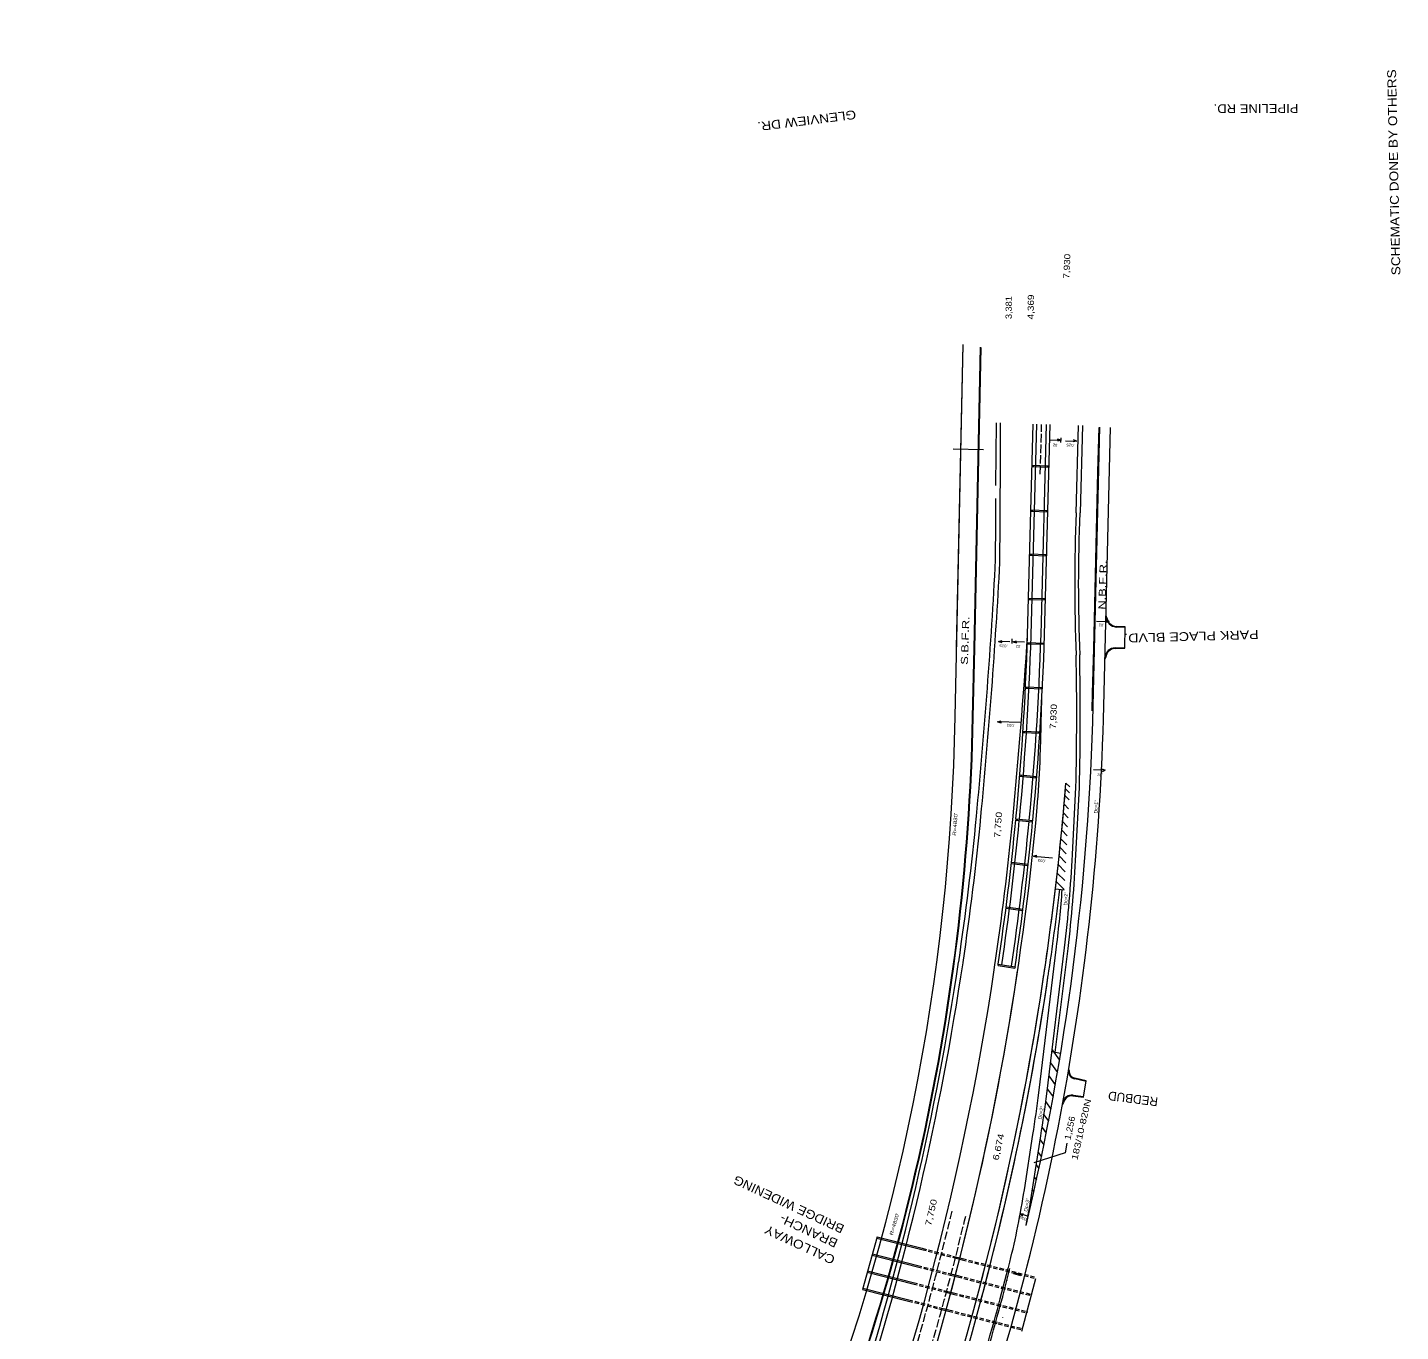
# Model space of a CAD drawing. Extents: x 2354993 to 2372084, y 6966390 to 6990057.
# Drawn here: x 2364099 to 2367196, y 6983254 to 6986197 of the extents above; entities that cross this region are included whole.
import ezdxf

# ---------------------------------------------------------------- set-up
doc = ezdxf.new("R2010")
doc.units = 0
doc.header["$LTSCALE"] = 3.2
doc.linetypes.add('LONG_DASHED', pattern=[7.5, 6, -1.5])
doc.linetypes.add('MEDIUM_DASHED', pattern=[4.5, 3, -1.5])
for name, color, linetype, lineweight in [('11', 7, 'Continuous', 13), ('12', 7, 'Continuous', 13), ('13', 7, 'Continuous', 13), ('19', 7, 'Continuous', 13), ('25', 7, 'Continuous', 13), ('4', 7, 'Continuous', 13), ('40', 7, 'Continuous', 13), ('5', 7, 'Continuous', 13), ('6', 7, 'Continuous', 13), ('63', 7, 'Continuous', 13), ('7', 7, 'Continuous', 13), ('8', 7, 'Continuous', 13), ('9', 7, 'Continuous', 13)]:
    doc.layers.add(name, color=color, linetype=linetype, lineweight=lineweight)

msp = doc.modelspace()

# ---------------------------------------------------------------- linework, layer by layer
at = {"layer": '11'}
for p, q in [((2366538.791, 6984856.255), (2366530.724, 6984854.262)), ((2366529.954, 6984521.156), (2366503.645, 6984521.922)), ((2366523.004, 6984523.998), (2366529.954, 6984521.156)), ((2366523.876, 6984518.238), (2366529.954, 6984521.156))]:
    msp.add_line(p, q, dxfattribs=at)
msp.add_lwpolyline([(2366510.454, 6984857.25), (2366538.791, 6984856.255), (2366530.884, 6984858.81)], dxfattribs=at)
at = {"layer": '12'}
for p, q in [((2366364.888, 6985208.936), (2366364.805, 6985205.936)), ((2366364.805, 6985205.936), (2366403.044, 6985204.915)), ((2366364.888, 6985208.936), (2366403.118, 6985207.914)), ((2366367.987, 6985208.85), (2366367.904, 6985205.85)), ((2366399.945, 6985204.992), (2366400.019, 6985207.991)), ((2366403.044, 6985204.915), (2366403.118, 6985207.914)), ((2366362.436, 6985108.243), (2366362.353, 6985105.243)), ((2366362.353, 6985105.243), (2366400.592, 6985104.222)), ((2366362.436, 6985108.243), (2366400.666, 6985107.221)), ((2366365.535, 6985108.157), (2366365.452, 6985105.157)), ((2366397.493, 6985104.299), (2366397.567, 6985107.298)), ((2366400.592, 6985104.222), (2366400.666, 6985107.221)), ((2366359.998, 6985008.861), (2366359.915, 6985005.861)), ((2366359.915, 6985005.861), (2366398.154, 6985004.84)), ((2366359.998, 6985008.861), (2366398.228, 6985007.839)), ((2366363.097, 6985008.775), (2366363.014, 6985005.775)), ((2366395.055, 6985004.917), (2366395.129, 6985007.916)), ((2366398.154, 6985004.84), (2366398.228, 6985007.839)), ((2366357.049, 6984909.117), (2366356.966, 6984906.117)), ((2366356.966, 6984906.117), (2366395.205, 6984905.096)), ((2366357.049, 6984909.117), (2366395.279, 6984908.095)), ((2366360.148, 6984909.031), (2366360.065, 6984906.031)), ((2366392.106, 6984905.173), (2366392.18, 6984908.172)), ((2366395.205, 6984905.096), (2366395.279, 6984908.095)), ((2366354.588, 6984808.904), (2366354.505, 6984805.904)), ((2366354.505, 6984805.904), (2366392.744, 6984804.883)), ((2366354.588, 6984808.904), (2366392.818, 6984807.882)), ((2366357.687, 6984808.818), (2366357.604, 6984805.818)), ((2366389.645, 6984804.96), (2366389.719, 6984807.959)), ((2366392.744, 6984804.883), (2366392.818, 6984807.882)), ((2366350.209, 6984708.655), (2366350.126, 6984705.655)), ((2366350.126, 6984705.655), (2366388.365, 6984704.634)), ((2366350.209, 6984708.655), (2366388.439, 6984707.633)), ((2366353.308, 6984708.569), (2366353.225, 6984705.569)), ((2366385.266, 6984704.711), (2366385.34, 6984707.71)), ((2366388.365, 6984704.634), (2366388.439, 6984707.633)), ((2366344.53, 6984608.98), (2366344.406, 6984605.981)), ((2366344.406, 6984605.981), (2366382.629, 6984604.439)), ((2366344.53, 6984608.98), (2366382.743, 6984607.436)), ((2366347.628, 6984608.852), (2366347.504, 6984605.853)), ((2366379.531, 6984604.558), (2366379.646, 6984607.555)), ((2366382.629, 6984604.439), (2366382.743, 6984607.436)), ((2366338.161, 6984510.231), (2366337.864, 6984507.244)), ((2366338.161, 6984510.231), (2366376.221, 6984506.482)), ((2366341.246, 6984509.924), (2366340.949, 6984506.937)), ((2366337.864, 6984507.244), (2366375.933, 6984503.496)), ((2366372.847, 6984503.794), (2366373.135, 6984506.78)), ((2366375.933, 6984503.496), (2366376.221, 6984506.482)), ((2366328.743, 6984410.781), (2366328.446, 6984407.794)), ((2366328.446, 6984407.794), (2366366.515, 6984404.046)), ((2366328.743, 6984410.781), (2366366.803, 6984407.032)), ((2366331.828, 6984410.474), (2366331.531, 6984407.487)), ((2366363.429, 6984404.344), (2366363.717, 6984407.33)), ((2366366.515, 6984404.046), (2366366.803, 6984407.032)), ((2366318.344, 6984310.299), (2366356.373, 6984306.191)), ((2366318.666, 6984313.282), (2366356.695, 6984309.174)), ((2366306.287, 6984209.38), (2366344.232, 6984204.566)), ((2366306.665, 6984212.356), (2366344.611, 6984207.542)), ((2366288.504, 6984080.134), (2366288.942, 6984083.102)), ((2366288.504, 6984080.134), (2366326.343, 6984074.539)), ((2366288.942, 6984083.102), (2366326.781, 6984077.507)), ((2366326.781, 6984077.507), (2366326.343, 6984074.539)), ((2366015.164, 6983465.056), (2366116.698, 6983439.228)), ((2366015.904, 6983467.964), (2366117.457, 6983442.131)), ((2366004.286, 6983426.55), (2366106.578, 6983400.527)), ((2366005.097, 6983429.441), (2366107.337, 6983403.431)), ((2366186.244, 6983424.631), (2366208.214, 6983419.041)), ((2366185.481, 6983421.728), (2366207.447, 6983416.14)), ((2366306.379, 6983394.068), (2366312.798, 6983392.434)), ((2365993.478, 6983388.025), (2366096.459, 6983361.827)), ((2365994.288, 6983390.915), (2366097.218, 6983364.731)), ((2366175.316, 6983383.04), (2366197.226, 6983377.466)), ((2366176.078, 6983385.942), (2366197.993, 6983380.366)), ((2366305.608, 6983391.166), (2366312.143, 6983389.503)), ((2366323.39, 6983384.946), (2366339.177, 6983380.553)), ((2366324.132, 6983387.855), (2366339.955, 6983383.452)), ((2366342.248, 6983255.14), (2366373.814, 6983374.03)), ((2365982.67, 6983349.503), (2366086.339, 6983323.127)), ((2365983.481, 6983352.393), (2366087.098, 6983326.03)), ((2366165.15, 6983344.352), (2366187.006, 6983338.792)), ((2366165.913, 6983347.255), (2366187.773, 6983341.694)), ((2366295.329, 6983352.508), (2366303.407, 6983350.453)), ((2366296.1, 6983355.408), (2366304.062, 6983353.382)), ((2366154.985, 6983305.663), (2366176.785, 6983300.117)), ((2366155.748, 6983308.565), (2366177.552, 6983303.018)), ((2366285.049, 6983313.848), (2366294.672, 6983311.4)), ((2366285.821, 6983316.75), (2366295.327, 6983314.331)), ((2366274.77, 6983275.189), (2366285.936, 6983272.348)), ((2366275.541, 6983278.088), (2366286.591, 6983275.277))]:
    msp.add_line(p, q, dxfattribs=at)
at = {"layer": '12', "linetype": 'MEDIUM_DASHED'}
for p, q in [((2366116.698, 6983439.227), (2366185.481, 6983421.728)), ((2366117.457, 6983442.13), (2366186.244, 6983424.631)), ((2366106.578, 6983400.528), (2366175.316, 6983383.04)), ((2366107.337, 6983403.43), (2366176.078, 6983385.942)), ((2366207.447, 6983416.139), (2366369.811, 6983374.832)), ((2366208.214, 6983419.041), (2366371.427, 6983377.518)), ((2366096.458, 6983361.827), (2366165.15, 6983344.351)), ((2366097.218, 6983364.731), (2366165.913, 6983347.255)), ((2366197.226, 6983377.466), (2366360.946, 6983335.815)), ((2366197.993, 6983380.367), (2366360.785, 6983338.95)), ((2366187.006, 6983338.791), (2366354.02, 6983296.302)), ((2366187.773, 6983341.694), (2366355.61, 6983298.995)), ((2366086.339, 6983323.127), (2366154.985, 6983305.663)), ((2366087.098, 6983326.031), (2366155.748, 6983308.565)), ((2366176.785, 6983300.117), (2366343.594, 6983257.678)), ((2366177.552, 6983303.018), (2366344.357, 6983260.58))]:
    msp.add_line(p, q, dxfattribs=at)
at = {"layer": '12'}
for radius, start, end in [(6480.875, 351.616, 354.50799), (6488.875, 351.616, 354.50799), (6511.125, 351.61584, 354.50723), (6519.125, 351.61584, 354.50723)]:
    msp.add_arc((2359877.328, 6985028.058), radius, start, end, dxfattribs=at)
at = {"layer": '19'}
for p, q in [((2366430.521, 6985265.56), (2366422.451, 6985263.573)), ((2366430.174, 6985260.343), (2366430.481, 6985271.185)), ((2366466.196, 6985263.41), (2366458.126, 6985261.423)), ((2366289.386, 6984811.585), (2366297.456, 6984813.571)), ((2366319.615, 6984817.313), (2366319.461, 6984806.469)), ((2366322.246, 6984810.631), (2366330.316, 6984812.617)), ((2366287.333, 6984630.065), (2366295.39, 6984632.098)), ((2366376.305, 6984328.318), (2366368.138, 6984326.78)), ((2366368.138, 6984326.78), (2366411.423, 6984322.823)), ((2366375.889, 6984323.785), (2366368.138, 6984326.78)), ((2366337.6, 6983520.462), (2366344.344, 6983515.613)), ((2366337.6, 6983520.462), (2366345.892, 6983519.893)), ((2366354.54, 6983514.355), (2366337.6, 6983520.462))]:
    msp.add_line(p, q, dxfattribs=at)
for points in [[(2366404.755, 6985266.491), (2366430.521, 6985265.56), (2366422.62, 6985268.122)], [(2366440.43, 6985264.341), (2366466.196, 6985263.41), (2366458.295, 6985265.972)], [(2366315.152, 6984810.653), (2366289.386, 6984811.585), (2366297.287, 6984809.023)], [(2366348.012, 6984809.699), (2366322.246, 6984810.631), (2366330.147, 6984808.069)], [(2366339.317, 6984628.497), (2366287.333, 6984630.065), (2366295.252, 6984627.549)]]:
    msp.add_lwpolyline(points, dxfattribs=at)
at = {"layer": '25'}
for p, q in [((2366191.602, 6984641.522), (2366209.421, 6985481.658)), ((2366194.919, 6984797.945), (2366209.421, 6985481.658)), ((2366234.353, 6984795.684), (2366248.866, 6985475.047)), ((2366235.853, 6984795.652), (2366250.366, 6985475.015)), ((2366355.875, 6984854.36), (2366367.65, 6985301.542)), ((2366363.872, 6984854.149), (2366375.647, 6985301.331)), ((2366386.165, 6984855.466), (2366397.891, 6985300.747)), ((2366394.162, 6984855.255), (2366405.888, 6985300.536)), ((2366503.056, 6984666.009), (2366518.337, 6985295.092)), ((2366527.049, 6984665.426), (2366542.33, 6985294.509)), ((2366533.393, 6984866.222), (2366532.269, 6984872.365)), ((2366574.915, 6984842.827), (2366554.717, 6984843.989)), ((2366575.001, 6984844.324), (2366554.803, 6984845.486)), ((2366574.75, 6984796.484), (2366575.001, 6984844.324)), ((2366231.093, 6984640.684), (2366234.353, 6984795.684)), ((2366232.593, 6984640.652), (2366235.853, 6984795.652)), ((2366552.445, 6984796.946), (2366574.68, 6984797.983)), ((2366552.515, 6984795.448), (2366574.75, 6984796.484)), ((2366531.595, 6984775.836), (2366529.681, 6984771.371)), ((2366456.176, 6984330.491), (2366464.117, 6984482.295)), ((2366456.176, 6984330.491), (2366464.117, 6984482.295)), ((2366464.165, 6984330.073), (2366472.106, 6984481.877)), ((2366417.588, 6983883.842), (2366446.247, 6984118.848)), ((2366449.098, 6983843.616), (2366448.408, 6983847.851)), ((2366487.173, 6983818.766), (2366461.659, 6983824.757)), ((2366487.516, 6983820.226), (2366462.002, 6983826.217)), ((2366480.99, 6983782.813), (2366487.516, 6983820.226)), ((2366436.219, 6983770.765), (2366434.12, 6983767.703)), ((2366457.408, 6983786.42), (2366480.99, 6983782.813)), ((2366457.635, 6983787.903), (2366481.217, 6983784.295)), ((2366015.905, 6983467.966), (2365982.67, 6983349.503)), ((2366299.124, 6983285.604), (2366299.2, 6983286.601))]:
    msp.add_line(p, q, dxfattribs=at)
for points in [[(2366504.178, 6984794.577), (2366506.607, 6984894.547), (2366509.035, 6984994.518), (2366511.463, 6985094.488), (2366513.892, 6985194.459), (2366516.32, 6985294.429)], [(2366500.792, 6984655.165), (2366501.75, 6984694.606), (2366504.178, 6984794.577)]]:
    msp.add_lwpolyline(points, dxfattribs=at)
for centre, radius, start, end in [((2370574.042, 6984940.976), 4112.509, 177.76241, 182.23376), ((2370574.042, 6984940.976), 4104.509, 177.76241, 182.23376), ((2359877.328, 6985028.058), 6480.875, 354.53443, 358.4642), ((2359877.328, 6985028.058), 6488.875, 354.53443, 358.4642), ((2359877.328, 6985028.058), 6511.125, 354.53369, 358.48108), ((2359877.328, 6985028.058), 6519.125, 354.53369, 358.48108), ((2366556.863, 6984869.035), 25.138, 186.83461, 265.10234), ((2366556.863, 6984869.035), 23.638, 186.83461, 265.10234), ((2366552.807, 6984774.171), 22.778, 90.91053, 175.51359), ((2366552.807, 6984774.171), 21.278, 90.91053, 175.51359), ((2359312.852, 6984644.469), 7161.104, 358.6944, 1.09115), ((2346853.406, 6985149.675), 19539.408, 358.20923, 358.62401), ((2361244.215, 6984746.454), 4988, 335.74923, 358.78496), ((2361244.215, 6984746.454), 4989.5, 335.74923, 358.78496), ((2361361.727, 6984722.767), 4830.559, 338.17176, 359.03629), ((2359877.328, 6985028.058), 6586.25, 353.24333, 355.09856), ((2359877.328, 6985028.058), 6586.25, 354.48323, 355.18157), ((2359877.328, 6985028.058), 6401.75, 351.54561, 354.5185), ((2359877.328, 6985028.058), 6473.75, 351.54561, 354.5185), ((2363580.688, 6984468.307), 2886.789, 353.04704, 357.25725), ((2359877.328, 6985028.058), 6586.25, 351.52586, 353.24333), ((2359877.328, 6985028.058), 6473.75, 337.9611, 351.54233), ((2359877.328, 6985028.057), 6526.25, 337.9611, 351.54396), ((2359877.328, 6985028.057), 6586.25, 337.9611, 351.54396), ((2359877.328, 6985028.057), 6596.25, 337.9611, 351.54396), ((2366464.179, 6983841.321), 16.755, 171.34788, 262.00973), ((2366464.179, 6983841.321), 15.255, 171.34788, 262.00973), ((2366455.784, 6983766.447), 21.536, 85.07046, 167.55399), ((2366455.784, 6983766.447), 20.036, 85.07046, 167.55399), ((2360811.157, 6984804.27), 5681.578, 345.37481, 345.37817)]:
    msp.add_arc(centre, radius, start, end, dxfattribs=at)
at = {"layer": '25', "linetype": 'LONG_DASHED'}
for centre, radius, end in [((2359877.328, 6985028.058), 6483.75, 346.60187), ((2359877.328, 6985028.057), 6516.25, 346.60718)]:
    msp.add_arc(centre, radius, 337.9611, end, dxfattribs=at)
at = {"layer": '25'}
msp.add_ellipse((2359801.786, 6985036.219), major_axis=(6478.123, 0), ratio=0.996776, start_param=5.97499933, end_param=6.13557103, dxfattribs=at)
at = {"layer": '4'}
for p, q in [((2366283.609, 6985162.922), (2366284.777, 6985305.032)), ((2366293.961, 6985234.465), (2366294.256, 6985304.512)), ((2366293.087, 6985079.285), (2366293.961, 6985234.465)), ((2366292.754, 6984989.792), (2366293.087, 6985079.285))]:
    msp.add_line(p, q, dxfattribs=at)
msp.add_lwpolyline([(2366282.681, 6984988.24), (2366282.785, 6985022.102), (2366283.108, 6985052.593), (2366283.2, 6985087.074), (2366283.645, 6985133.964)], dxfattribs=at)
for centre, radius, start, end in [((2352371.567, 6985744.582), 13931.634, 354.53186, 356.91694), ((2352371.567, 6985744.582), 13941.634, 354.53186, 356.89653), ((2352371.567, 6985744.582), 14013.634, 354.53186, 356.24046), ((2359877.328, 6985028.058), 6391.75, 351.54561, 354.51414), ((2359877.328, 6985028.058), 6391.75, 342.25932, 351.54233)]:
    msp.add_arc(centre, radius, start, end, dxfattribs=at)
at = {"layer": '40', "linetype": 'LONG_DASHED'}
msp.add_line((2366383.808, 6985188.613), (2366386.769, 6985301.039), dxfattribs=at)
at = {"layer": '40'}
for p, q in [((2366464.669, 6985101.543), (2366469.865, 6985298.851)), ((2366474.666, 6985101.28), (2366479.862, 6985298.588))]:
    msp.add_line(p, q, dxfattribs=at)
at = {"layer": '5'}
for p, q in [((2366449.462, 6984470.141), (2366440.66, 6984479.098)), ((2366450.136, 6984483.026), (2366441.695, 6984491.613)), ((2366448.633, 6984454.299), (2366439.358, 6984463.738)), ((2366446.508, 6984413.673), (2366435.865, 6984424.498)), ((2366447.571, 6984433.986), (2366437.638, 6984444.092)), ((2366444.382, 6984373.037), (2366432.156, 6984385.475)), ((2366445.445, 6984393.356), (2366434.037, 6984404.961)), ((2366443.32, 6984352.721), (2366430.223, 6984366.045)), ((2366441.214, 6984312.071), (2366426.198, 6984327.346)), ((2366442.257, 6984332.407), (2366428.236, 6984346.67)), ((2366440.039, 6984291.868), (2366424.107, 6984308.074)), ((2366437.29, 6984251.873), (2366419.772, 6984269.691)), ((2366438.73, 6984271.803), (2366421.965, 6984288.857)), ((2366417.835, 6984253.165), (2366437.241, 6984251.233)), ((2366380.341, 6983793.189), (2366420.438, 6984121.995)), ((2366398.208, 6983791.01), (2366438.306, 6984119.816)), ((2366410.241, 6983889.678), (2366426.954, 6983866.372)), ((2366406.664, 6983860.347), (2366422.248, 6983838.616)), ((2366429.523, 6983881.883), (2366409.787, 6983885.123)), ((2366403.087, 6983831.017), (2366417.429, 6983811.018)), ((2366399.51, 6983801.686), (2366412.498, 6983783.576)), ((2366395.881, 6983772.428), (2366407.456, 6983756.287)), ((2366392.013, 6983743.503), (2366402.306, 6983729.15)), ((2366387.898, 6983714.923), (2366397.049, 6983702.162)), ((2366347.754, 6983573.93), (2366367.202, 6983698.615)), ((2366365.539, 6983571.156), (2366384.987, 6983695.841)), ((2366383.555, 6983686.66), (2366391.686, 6983675.321)), ((2366379.158, 6983658.472), (2366386.219, 6983648.626)), ((2366374.762, 6983630.284), (2366380.649, 6983622.074)), ((2366370.365, 6983602.096), (2366374.978, 6983595.664)), ((2366365.969, 6983573.908), (2366369.206, 6983569.393)), ((2366293.589, 6983328.522), (2366311.43, 6983397.183)), ((2366297.461, 6983327.516), (2366315.301, 6983396.177)), ((2366311.209, 6983395.611), (2366314.99, 6983410.926))]:
    msp.add_line(p, q, dxfattribs=at)
msp.add_lwpolyline([(2366443.757, 6983679.208), (2366440.171, 6983657.357), (2366369.094, 6983635.235)], dxfattribs=at)
for centre, radius, start, end in [((2360811.157, 6984804.27), 5717.578, 339.9908, 358.60851), ((2360811.157, 6984804.27), 5693.578, 346.6878, 358.60851), ((2362514.248, 6984735.032), 3873.983, 355.57895, 357.10053), ((2359877.328, 6985028.058), 6586.25, 344.87929, 355.32812), ((2359877.328, 6985028.058), 6526.25, 344.87929, 354.79857), ((2363580.688, 6984468.302), 2878.789, 353.04712, 357.25735), ((2359877.328, 6985028.058), 6596.25, 351.52586, 353.24495), ((2363580.688, 6984468.302), 2860.789, 353.04712, 355.65632), ((2359877.328, 6985028.057), 6596.25, 344.87918, 351.54396), ((2363540.59, 6984139.496), 2860.789, 351.1347, 353.04712), ((2363540.59, 6984139.496), 2878.789, 351.1347, 353.04712), ((2364464.664, 6983867.646), 1905.859, 346.1347, 351.1347), ((2364464.664, 6983867.646), 1923.859, 348.77927, 351.1347), ((2360811.157, 6984804.27), 5677.578, 339.99081, 344.99116), ((2360811.157, 6984804.27), 5681.578, 339.99081, 344.99116)]:
    msp.add_arc(centre, radius, start, end, dxfattribs=at)
at = {"layer": '6'}
msp.add_arc((2359312.852, 6984644.469), 7153.104, 358.6944, 1.09115, dxfattribs=at)
at = {"layer": '8'}
msp.add_line((2366255.472, 6985244.095), (2366187.376, 6985244.954), dxfattribs=at)
at = {"layer": '9'}
msp.add_arc((2360722.521, 6984327.136), 5729.573, 359.50797, 359.50797, dxfattribs=at)

# ---------------------------------------------------------------- texts
at = {"layer": '13'}
for s, height, rotation, width, p in [('GLENVIEW DR.', 20, 187.098, 1.15, (2365966.815, 6986010.487)), ('PIPELINE RD.', 20, 180.198, 1.1, (2366966.075, 6986024.063)), ('N.B.F.R.', 16, 88.194, 1.35, (2366530.474, 6984883.069)), ('S.B.F.R.', 16, 88.194, 1.35, (2366220.301, 6984758.646)), ('PARK PLACE BLVD.', 20, 181.585, 1.2, (2366875.957, 6984837.023)), ('7,930', 14, 87.365, 1.2, (2366418.843, 6984613.738)), ('7,750', 14, 85.224, 1.25, (2366292.854, 6984367.979)), ('183/10-820N ', 14, 77.104, 1.3, (2366467.227, 6983640.224)), ('1,256', 14, 77.763, 1.15, (2366451.533, 6983685.835)), ('6,674', 14, 77.487, 1.3, (2366289.228, 6983639.46)), ('BRIDGE WIDENING', 20, 155.121, 1.1, (2365943.471, 6983493.184)), ('7,750', 14, 76.953, 1.3, (2366137.322, 6983491.861)), ('CALLOWAY', 20, 155.121, 1.15, (2365922.831, 6983423.18)), ('BRANCH-', 20, 155.121, 1.15, (2365929.131, 6983460.948))]:
    msp.add_text(s, height=height, rotation=rotation, dxfattribs=dict(at, width=width)).set_placement(p)
msp.add_text('REDBUD', height=20, rotation=172.734, dxfattribs=at).set_placement((2366650.238, 6983782.238))
at = {"layer": '19'}
for s, height, rotation, width, p in [('.02', 5.999, 177.853, 1.1, (2366424.573, 6985257.118)), ('.025', 6, 176.541, 1.2, (2366461.735, 6985256.76)), ('.02', 5.999, 177.689, 1.1, (2366527.861, 6984851.17)), ('.025', 5.999, 176.112, 1.2, (2366310.17, 6984803.739)), ('.02', 6, 179.189, 1.05, (2366340.492, 6984803.303)), ('.033', 5.999, 176.39, 1.2, (2366326.848, 6984624.444)), ('.02', 5.999, 175.689, 1.1, (2366524.98, 6984512.782)), ('Dc=1°', 8, 87.297, 0.95, (2366512.665, 6984423.288)), ('.033', 6, 172.955, 1.2, (2366396.927, 6984318.53)), ('Dc=2°', 8, 79.394, 1.05, (2366386.109, 6983732.411)), ('Dc=3°', 8, 79.394, 1.05, (2366354.312, 6983524.254)), ('.039', 6, 160.217, 1.25, (2366356.161, 6983508.93))]:
    msp.add_text(s, height=height, rotation=rotation, dxfattribs=dict(at, width=width)).set_placement(p)
msp.add_text('Dc=2°', height=8, rotation=87.297, dxfattribs=at).set_placement((2366444.683, 6984215.595))
at = {"layer": '63'}
for s, height, rotation, width, p in [('SCHEMATIC DONE BY OTHERS', 20, 91.231, 1.15, (2367196.197, 6985637.787)), ('7,930', 14, 87.365, 1.2, (2366449.31, 6985629.536)), ('4,369', 14, 89.12, 1.2, (2366368.747, 6985537.812)), ('3,381', 14, 89.847, 1.1, (2366319.343, 6985538.865))]:
    msp.add_text(s, height=height, rotation=rotation, dxfattribs=dict(at, width=width)).set_placement(p)
at = {"layer": '7', "width": 1.3}
for rotation, p in [(86.009, (2366193.607, 6984372.876)), (74.106, (2366051.268, 6983470.901))]:
    msp.add_text("R=4830'", height=8, rotation=rotation, dxfattribs=at).set_placement(p)

doc.saveas('drawing.dxf')
